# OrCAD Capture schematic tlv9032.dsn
size A
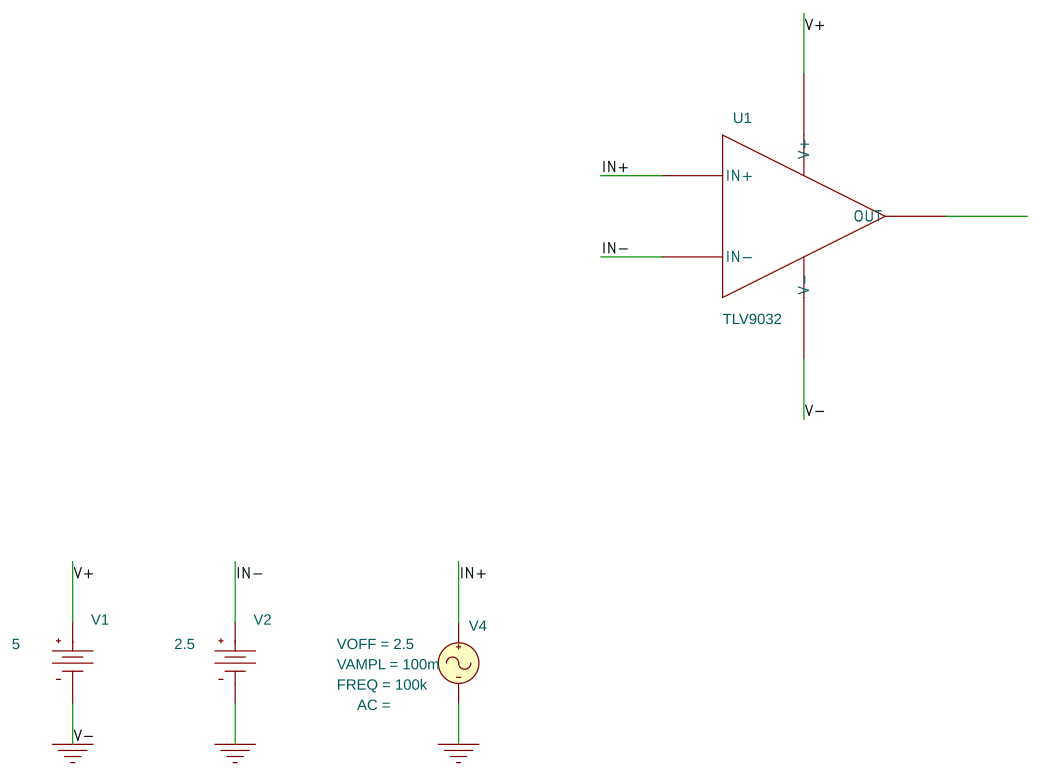
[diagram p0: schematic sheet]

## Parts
U1  TLV9032
V1  VDC
V2  VDC
V4  VSIN

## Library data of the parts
U1 = TLV9032
V1 = VDC: DC: 5
V2 = VDC: DC: 2.5
V4 = VSIN: FREQ: 100k; VAMPL: 100m; VOFF: 2.5

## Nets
0: U1.V- V1.1(-) V2.1(-) V4.2(-)
IN+: U1.IN+ V4.1(+)
IN-: U1.IN- V2.0(+)
V+: U1.V+ V1.0(+)

Not connected (* = marked no-connect by the designer): U1 OUT
